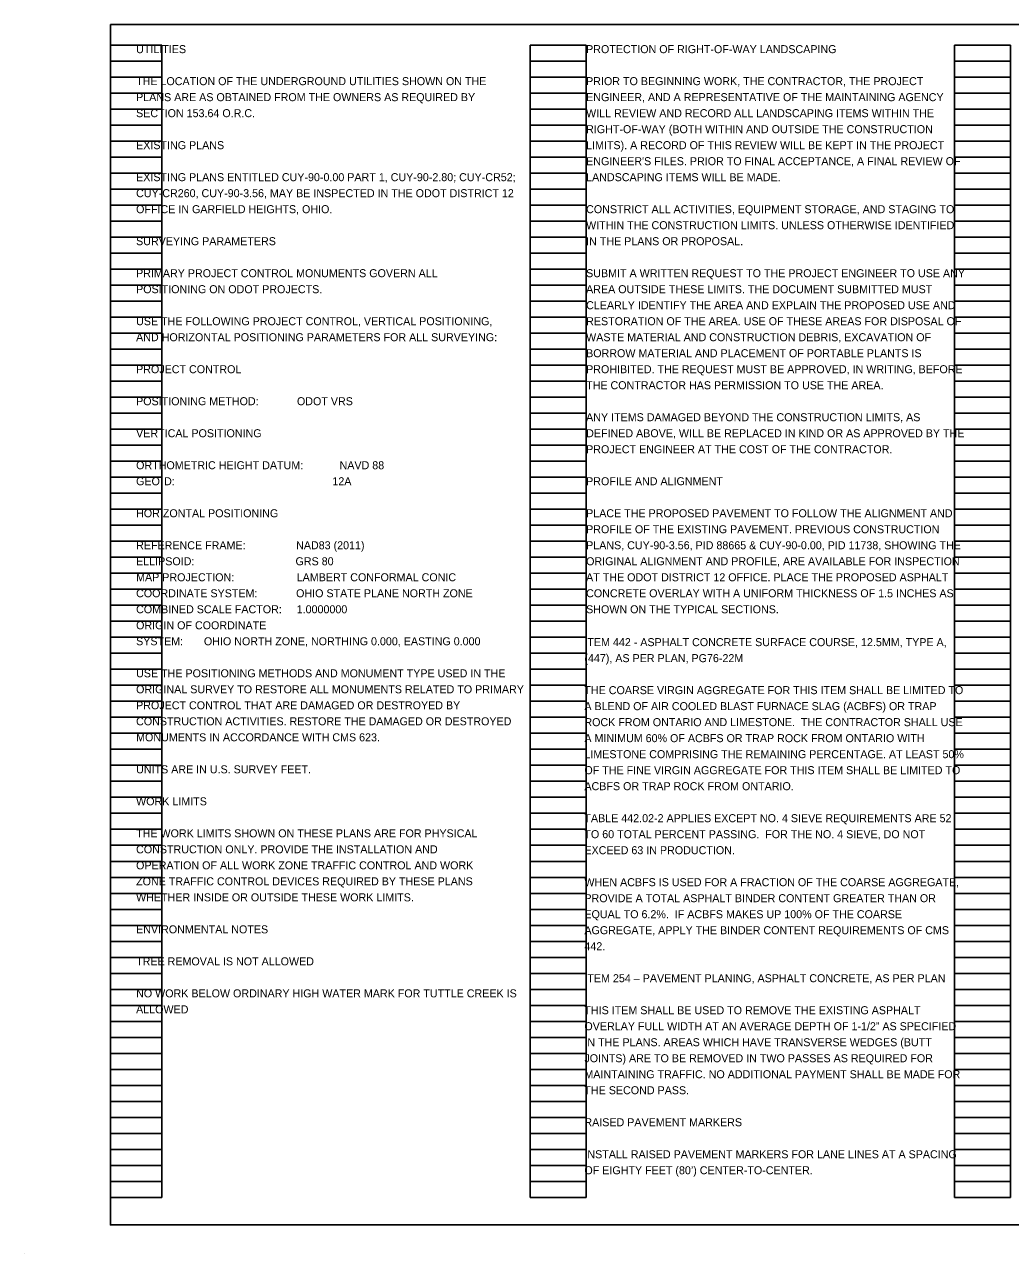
# Model space of a CAD drawing. Extents: x 0 to 2132911, y 0 to 658646.
# Drawn here: x 0 to 17.24, y 0 to 21.5 of the extents above; entities that cross this region are included whole.
import ezdxf

# ---------------------------------------------------------------- set-up
doc = ezdxf.new("R2010")
doc.units = 0
for name, color, linetype in [('SC_Scratch1', 7, 'Continuous'), ('SH_Data', 7, 'Continuous'), ('SH_Text', 7, 'Continuous')]:
    doc.layers.add(name, color=color, linetype=linetype)

msp = doc.modelspace()

# ---------------------------------------------------------------- linework, layer by layer
at = {"layer": 'SC_Scratch1'}
msp.add_lwpolyline([(1.5, 21.5), (32, 21.5), (32, 0.5), (1.5, 0.5)], close=True, dxfattribs=at)
at = {"layer": 'SH_Data'}
for p, q in [((1.5, 0.98), (1.5, 21.14)), ((1.5, 21.14), (2.4, 21.14)), ((2.4, 0.98), (2.4, 21.14)), ((8.84, 0.98), (8.84, 21.14)), ((8.84, 21.14), (9.82, 21.14)), ((9.82, 0.98), (9.82, 21.14)), ((16.26, 0.98), (16.26, 21.14)), ((16.26, 21.14), (17.24, 21.14)), ((17.24, 0.98), (17.24, 21.14)), ((1.5, 20.86), (2.4, 20.86)), ((8.84, 20.86), (9.82, 20.86)), ((16.26, 20.86), (17.24, 20.86)), ((1.5, 20.58), (2.4, 20.58)), ((8.84, 20.58), (9.82, 20.58)), ((16.26, 20.58), (17.24, 20.58)), ((1.5, 20.3), (2.4, 20.3)), ((8.84, 20.3), (9.82, 20.3)), ((16.26, 20.3), (17.24, 20.3)), ((1.5, 20.02), (2.4, 20.02)), ((8.84, 20.02), (9.82, 20.02)), ((16.26, 20.02), (17.24, 20.02)), ((1.5, 19.74), (2.4, 19.74)), ((8.84, 19.74), (9.82, 19.74)), ((16.26, 19.74), (17.24, 19.74)), ((1.5, 19.46), (2.4, 19.46)), ((8.84, 19.46), (9.82, 19.46)), ((16.26, 19.46), (17.24, 19.46)), ((1.5, 19.18), (2.4, 19.18)), ((8.84, 19.18), (9.82, 19.18)), ((16.26, 19.18), (17.24, 19.18)), ((1.5, 18.9), (2.4, 18.9)), ((8.84, 18.9), (9.82, 18.9)), ((16.26, 18.9), (17.24, 18.9)), ((1.5, 18.62), (2.4, 18.62)), ((8.84, 18.62), (9.82, 18.62)), ((16.26, 18.62), (17.24, 18.62)), ((1.5, 18.34), (2.4, 18.34)), ((8.84, 18.34), (9.82, 18.34)), ((16.26, 18.34), (17.24, 18.34)), ((1.5, 18.06), (2.4, 18.06)), ((8.84, 18.06), (9.82, 18.06)), ((16.26, 18.06), (17.24, 18.06)), ((1.5, 17.78), (2.4, 17.78)), ((8.84, 17.78), (9.82, 17.78)), ((16.26, 17.78), (17.24, 17.78)), ((1.5, 17.5), (2.4, 17.5)), ((8.84, 17.5), (9.82, 17.5)), ((16.26, 17.5), (17.24, 17.5)), ((1.5, 17.22), (2.4, 17.22)), ((8.84, 17.22), (9.82, 17.22)), ((16.26, 17.22), (17.24, 17.22)), ((1.5, 16.94), (2.4, 16.94)), ((8.84, 16.94), (9.82, 16.94)), ((16.26, 16.94), (17.24, 16.94)), ((1.5, 16.66), (2.4, 16.66)), ((8.84, 16.66), (9.82, 16.66)), ((16.26, 16.66), (17.24, 16.66)), ((1.5, 16.38), (2.4, 16.38)), ((8.84, 16.38), (9.82, 16.38)), ((16.26, 16.38), (17.24, 16.38)), ((1.5, 16.1), (2.4, 16.1)), ((8.84, 16.1), (9.82, 16.1)), ((16.26, 16.1), (17.24, 16.1)), ((1.5, 15.82), (2.4, 15.82)), ((8.84, 15.82), (9.82, 15.82)), ((16.26, 15.82), (17.24, 15.82)), ((1.5, 15.54), (2.4, 15.54)), ((8.84, 15.54), (9.82, 15.54)), ((16.26, 15.54), (17.24, 15.54)), ((1.5, 15.26), (2.4, 15.26)), ((8.84, 15.26), (9.82, 15.26)), ((16.26, 15.26), (17.24, 15.26)), ((1.5, 14.98), (2.4, 14.98)), ((8.84, 14.98), (9.82, 14.98)), ((16.26, 14.98), (17.24, 14.98)), ((1.5, 14.7), (2.4, 14.7)), ((8.84, 14.7), (9.82, 14.7)), ((16.26, 14.7), (17.24, 14.7)), ((1.5, 14.42), (2.4, 14.42)), ((8.84, 14.42), (9.82, 14.42)), ((16.26, 14.42), (17.24, 14.42)), ((1.5, 14.14), (2.4, 14.14)), ((8.84, 14.14), (9.82, 14.14)), ((16.26, 14.14), (17.24, 14.14)), ((1.5, 13.86), (2.4, 13.86)), ((8.84, 13.86), (9.82, 13.86)), ((16.26, 13.86), (17.24, 13.86)), ((1.5, 13.58), (2.4, 13.58)), ((8.84, 13.58), (9.82, 13.58)), ((16.26, 13.58), (17.24, 13.58)), ((1.5, 13.3), (2.4, 13.3)), ((8.84, 13.3), (9.82, 13.3)), ((16.26, 13.3), (17.24, 13.3)), ((1.5, 13.02), (2.4, 13.02)), ((8.84, 13.02), (9.82, 13.02)), ((16.26, 13.02), (17.24, 13.02)), ((1.5, 12.74), (2.4, 12.74)), ((8.84, 12.74), (9.82, 12.74)), ((16.26, 12.74), (17.24, 12.74)), ((1.5, 12.46), (2.4, 12.46)), ((8.84, 12.46), (9.82, 12.46)), ((16.26, 12.46), (17.24, 12.46)), ((1.5, 12.18), (2.4, 12.18)), ((8.84, 12.18), (9.82, 12.18)), ((16.26, 12.18), (17.24, 12.18)), ((1.5, 11.9), (2.4, 11.9)), ((8.84, 11.9), (9.82, 11.9)), ((16.26, 11.9), (17.24, 11.9)), ((1.5, 11.62), (2.4, 11.62)), ((8.84, 11.62), (9.82, 11.62)), ((16.26, 11.62), (17.24, 11.62)), ((1.5, 11.34), (2.4, 11.34)), ((8.84, 11.34), (9.82, 11.34)), ((16.26, 11.34), (17.24, 11.34)), ((1.5, 11.06), (2.4, 11.06)), ((8.84, 11.06), (9.82, 11.06)), ((16.26, 11.06), (17.24, 11.06)), ((1.5, 10.78), (2.4, 10.78)), ((8.84, 10.78), (9.82, 10.78)), ((16.26, 10.78), (17.24, 10.78)), ((1.5, 10.5), (2.4, 10.5)), ((8.84, 10.5), (9.82, 10.5)), ((16.26, 10.5), (17.24, 10.5)), ((1.5, 10.22), (2.4, 10.22)), ((8.84, 10.22), (9.82, 10.22)), ((16.26, 10.22), (17.24, 10.22)), ((1.5, 9.94), (2.4, 9.94)), ((8.84, 9.94), (9.82, 9.94)), ((16.26, 9.94), (17.24, 9.94)), ((1.5, 9.66), (2.4, 9.66)), ((8.84, 9.66), (9.82, 9.66)), ((16.26, 9.66), (17.24, 9.66)), ((1.5, 9.38), (2.4, 9.38)), ((8.84, 9.38), (9.82, 9.38)), ((16.26, 9.38), (17.24, 9.38)), ((1.5, 9.1), (2.4, 9.1)), ((8.84, 9.1), (9.82, 9.1)), ((16.26, 9.1), (17.24, 9.1)), ((1.5, 8.82), (2.4, 8.82)), ((8.84, 8.82), (9.82, 8.82)), ((16.26, 8.82), (17.24, 8.82)), ((1.5, 8.54), (2.4, 8.54)), ((8.84, 8.54), (9.82, 8.54)), ((16.26, 8.54), (17.24, 8.54)), ((1.5, 8.26), (2.4, 8.26)), ((8.84, 8.26), (9.82, 8.26)), ((16.26, 8.26), (17.24, 8.26)), ((1.5, 7.98), (2.4, 7.98)), ((8.84, 7.98), (9.82, 7.98)), ((16.26, 7.98), (17.24, 7.98)), ((1.5, 7.7), (2.4, 7.7)), ((8.84, 7.7), (9.82, 7.7)), ((16.26, 7.7), (17.24, 7.7)), ((1.5, 7.42), (2.4, 7.42)), ((8.84, 7.42), (9.82, 7.42)), ((16.26, 7.42), (17.24, 7.42)), ((1.5, 7.14), (2.4, 7.14)), ((8.84, 7.14), (9.82, 7.14)), ((16.26, 7.14), (17.24, 7.14)), ((1.5, 6.86), (2.4, 6.86)), ((8.84, 6.86), (9.82, 6.86)), ((16.26, 6.86), (17.24, 6.86)), ((1.5, 6.58), (2.4, 6.58)), ((8.84, 6.58), (9.82, 6.58)), ((16.26, 6.58), (17.24, 6.58)), ((1.5, 6.3), (2.4, 6.3)), ((8.84, 6.3), (9.82, 6.3)), ((16.26, 6.3), (17.24, 6.3)), ((1.5, 6.02), (2.4, 6.02)), ((8.84, 6.02), (9.82, 6.02)), ((16.26, 6.02), (17.24, 6.02)), ((1.5, 5.74), (2.4, 5.74)), ((8.84, 5.74), (9.82, 5.74)), ((16.26, 5.74), (17.24, 5.74)), ((1.5, 5.46), (2.4, 5.46)), ((8.84, 5.46), (9.82, 5.46)), ((16.26, 5.46), (17.24, 5.46)), ((1.5, 5.18), (2.4, 5.18)), ((8.84, 5.18), (9.82, 5.18)), ((16.26, 5.18), (17.24, 5.18)), ((1.5, 4.9), (2.4, 4.9)), ((8.84, 4.9), (9.82, 4.9)), ((16.26, 4.9), (17.24, 4.9)), ((1.5, 4.62), (2.4, 4.62)), ((8.84, 4.62), (9.82, 4.62)), ((16.26, 4.62), (17.24, 4.62)), ((1.5, 4.34), (2.4, 4.34)), ((8.84, 4.34), (9.82, 4.34)), ((16.26, 4.34), (17.24, 4.34)), ((1.5, 4.06), (2.4, 4.06)), ((8.84, 4.06), (9.82, 4.06)), ((16.26, 4.06), (17.24, 4.06)), ((1.5, 3.78), (2.4, 3.78)), ((8.84, 3.78), (9.82, 3.78)), ((16.26, 3.78), (17.24, 3.78)), ((1.5, 3.5), (2.4, 3.5)), ((8.84, 3.5), (9.82, 3.5)), ((16.26, 3.5), (17.24, 3.5)), ((1.5, 3.22), (2.4, 3.22)), ((8.84, 3.22), (9.82, 3.22)), ((16.26, 3.22), (17.24, 3.22)), ((1.5, 2.94), (2.4, 2.94)), ((8.84, 2.94), (9.82, 2.94)), ((16.26, 2.94), (17.24, 2.94)), ((1.5, 2.66), (2.4, 2.66)), ((8.84, 2.66), (9.82, 2.66)), ((16.26, 2.66), (17.24, 2.66)), ((1.5, 2.38), (2.4, 2.38)), ((8.84, 2.38), (9.82, 2.38)), ((16.26, 2.38), (17.24, 2.38)), ((1.5, 2.1), (2.4, 2.1)), ((8.84, 2.1), (9.82, 2.1)), ((16.26, 2.1), (17.24, 2.1)), ((1.5, 1.82), (2.4, 1.82)), ((8.84, 1.82), (9.82, 1.82)), ((16.26, 1.82), (17.24, 1.82)), ((1.5, 1.54), (2.4, 1.54)), ((8.84, 1.54), (9.82, 1.54)), ((16.26, 1.54), (17.24, 1.54)), ((1.5, 1.26), (2.4, 1.26)), ((8.84, 1.26), (9.82, 1.26)), ((16.26, 1.26), (17.24, 1.26)), ((1.5, 0.98), (2.4, 0.98)), ((8.84, 0.98), (9.82, 0.98)), ((16.26, 0.98), (17.24, 0.98)), ((0, 0), (0, 0))]:
    msp.add_line(p, q, dxfattribs=at)

# ---------------------------------------------------------------- texts
at = {"layer": 'SH_Text'}
for s, p in [('UTILITIES', (1.95, 21)), ('PROTECTION OF RIGHT-OF-WAY LANDSCAPING', (9.82, 21)), ('THE LOCATION OF THE UNDERGROUND UTILITIES SHOWN ON THE', (1.95, 20.44)), ('PRIOR TO BEGINNING WORK, THE CONTRACTOR, THE PROJECT ', (9.82, 20.44)), ('PLANS ARE AS OBTAINED FROM THE OWNERS AS REQUIRED BY', (1.95, 20.16)), ('ENGINEER, AND A REPRESENTATIVE OF THE MAINTAINING AGENCY ', (9.82, 20.16)), ('SECTION 153.64 O.R.C.', (1.95, 19.88)), ('WILL REVIEW AND RECORD ALL LANDSCAPING ITEMS WITHIN THE ', (9.82, 19.88)), ('RIGHT-OF-WAY (BOTH WITHIN AND OUTSIDE THE CONSTRUCTION ', (9.82, 19.6)), ('EXISTING PLANS', (1.95, 19.32)), ('LIMITS). A RECORD OF THIS REVIEW WILL BE KEPT IN THE PROJECT ', (9.82, 19.32)), ("ENGINEER'S FILES. PRIOR TO FINAL ACCEPTANCE, A FINAL REVIEW OF ", (9.82, 19.04)), ('EXISTING PLANS ENTITLED CUY-90-0.00 PART 1, CUY-90-2.80; CUY-CR52; ', (1.95, 18.76)), ('LANDSCAPING ITEMS WILL BE MADE.', (9.82, 18.76)), ('CUY-CR260, CUY-90-3.56, MAY BE INSPECTED IN THE ODOT DISTRICT 12 ', (1.95, 18.48)), ('OFFICE IN GARFIELD HEIGHTS, OHIO.', (1.95, 18.2)), ('CONSTRICT ALL ACTIVITIES, EQUIPMENT STORAGE, AND STAGING TO ', (9.82, 18.2)), ('WITHIN THE CONSTRUCTION LIMITS. UNLESS OTHERWISE IDENTIFIED ', (9.82, 17.92)), ('SURVEYING PARAMETERS', (1.95, 17.64)), ('IN THE PLANS OR PROPOSAL.', (9.82, 17.64)), ('PRIMARY PROJECT CONTROL MONUMENTS GOVERN ALL', (1.95, 17.08)), ('SUBMIT A WRITTEN REQUEST TO THE PROJECT ENGINEER TO USE ANY ', (9.82, 17.08)), ('POSITIONING ON ODOT PROJECTS. ', (1.95, 16.8)), ('AREA OUTSIDE THESE LIMITS. THE DOCUMENT SUBMITTED MUST ', (9.82, 16.8)), ('CLEARLY IDENTIFY THE AREA AND EXPLAIN THE PROPOSED USE AND ', (9.82, 16.52)), ('USE THE FOLLOWING PROJECT CONTROL, VERTICAL POSITIONING,', (1.95, 16.24)), ('RESTORATION OF THE AREA. USE OF THESE AREAS FOR DISPOSAL OF ', (9.82, 16.24)), ('AND HORIZONTAL POSITIONING PARAMETERS FOR ALL SURVEYING:', (1.95, 15.96)), ('WASTE MATERIAL AND CONSTRUCTION DEBRIS, EXCAVATION OF ', (9.82, 15.96)), ('BORROW MATERIAL AND PLACEMENT OF PORTABLE PLANTS IS ', (9.82, 15.68)), ('PROJECT CONTROL', (1.95, 15.4)), ('PROHIBITED. THE REQUEST MUST BE APPROVED, IN WRITING, BEFORE ', (9.82, 15.4)), ('THE CONTRACTOR HAS PERMISSION TO USE THE AREA.', (9.82, 15.12)), ('POSITIONING METHOD: ', (1.95, 14.84)), ('          ODOT VRS', (4.243, 14.84)), ('ANY ITEMS DAMAGED BEYOND THE CONSTRUCTION LIMITS, AS ', (9.82, 14.56)), ('VERTICAL POSITIONING', (1.95, 14.28)), ('DEFINED ABOVE, WILL BE REPLACED IN KIND OR AS APPROVED BY THE ', (9.82, 14.28)), ('PROJECT ENGINEER AT THE COST OF THE CONTRACTOR.', (9.82, 14)), ('ORTHOMETRIC HEIGHT DATUM: ', (1.95, 13.72)), ('         NAVD 88', (5.04, 13.72)), ('GEOI', (1.95, 13.44)), ('D:                                                     12A', (2.439, 13.44)), ('PROFILE AND ALIGNMENT', (9.82, 13.44)), ('HORIZONTAL POSITIONING', (1.95, 12.88)), ('PLACE THE PROPOSED PAVEMENT TO FOLLOW THE ALIGNMENT AND ', (9.82, 12.88)), ('PROFILE OF THE EXISTING PAVEMENT. PREVIOUS CONSTRUCTION ', (9.82, 12.6)), ('REFERENCE FRAME:                 NAD83 (2011)', (1.95, 12.32)), ('PLANS, CUY-90-3.56, PID 88665 & CUY-90-0.00, PID 11738, SHOWING THE ', (9.82, 12.32)), ('ELLIPSOID:                                  GRS 80', (1.95, 12.04)), ('ORIGINAL ALIGNMENT AND PROFILE, ARE AVAILABLE FOR INSPECTION ', (9.82, 12.04)), ('MAP PROJECTION:                     LAMBERT CONFORMAL CONIC', (1.95, 11.76)), ('AT THE ODOT DISTRICT 12 OFFICE. PLACE THE PROPOSED ASPHALT ', (9.82, 11.76)), ('COORDINATE SYSTEM:             OHIO STATE PLANE NORTH ZONE', (1.95, 11.48)), ('CONCRETE OVERLAY WITH A UNIFORM THICKNESS OF 1.5 INCHES AS ', (9.82, 11.48)), ('COMBINED SCALE FACTOR:     1.0000000', (1.95, 11.2)), ('SHOWN ON THE TYPICAL SECTIONS.', (9.82, 11.2)), ('ORIGIN OF COORDINATE', (1.95, 10.92)), ('SYSTEM:       OHIO NORTH ZONE, NORTHING 0.000, EASTING 0.000', (1.95, 10.64)), ('ITEM 442 - ASPHALT CONCRETE SURFACE COURSE, 12.5MM, TYPE A, ', (9.79, 10.625)), ('(447), AS PER PLAN, PG76-22M', (9.79, 10.345)), ('USE THE POSITIONING METHODS AND MONUMENT TYPE USED IN THE ', (1.95, 10.08)), ('ORIGINAL SURVEY TO RESTORE ALL MONUMENTS RELATED TO PRIMARY ', (1.95, 9.8)), ('THE COARSE VIRGIN AGGREGATE FOR THIS ITEM SHALL BE LIMITED TO ', (9.79, 9.785)), ('PROJECT CONTROL THAT ARE DAMAGED OR DESTROYED BY ', (1.95, 9.52)), ('A BLEND OF AIR COOLED BLAST FURNACE SLAG (ACBFS) OR TRAP ', (9.79, 9.505)), ('CONSTRUCTION ACTIVITIES. RESTORE THE DAMAGED OR DESTROYED ', (1.95, 9.24)), ('ROCK FROM ONTARIO AND LIMESTONE.  THE CONTRACTOR SHALL USE ', (9.79, 9.225)), ('MONUMENTS IN ACCORDANCE WITH CMS 623.', (1.95, 8.96)), ('A MINIMUM 60% OF ACBFS OR TRAP ROCK FROM ONTARIO WITH ', (9.79, 8.945)), ('LIMESTONE COMPRISING THE REMAINING PERCENTAGE. AT LEAST 50% ', (9.79, 8.665)), ('UNITS ARE IN U.S. SURVEY FEET.', (1.95, 8.4)), ('OF THE FINE VIRGIN AGGREGATE FOR THIS ITEM SHALL BE LIMITED TO ', (9.79, 8.385)), ('ACBFS OR TRAP ROCK FROM ONTARIO.', (9.79, 8.105)), ('WORK LIMITS', (1.95, 7.84)), ('TABLE 442.02-2 APPLIES EXCEPT NO. 4 SIEVE REQUIREMENTS ARE 52 ', (9.79, 7.545)), ('THE WORK LIMITS SHOWN ON THESE PLANS ARE FOR PHYSICAL', (1.95, 7.28)), ('TO 60 TOTAL PERCENT PASSING.  FOR THE NO. 4 SIEVE, DO NOT ', (9.79, 7.265)), ('CONSTRUCTION ONLY. PROVIDE THE INSTALLATION AND', (1.95, 7)), ('EXCEED 63 IN PRODUCTION.', (9.79, 6.985)), ('OPERATION OF ALL WORK ZONE TRAFFIC CONTROL AND WORK', (1.95, 6.72)), ('ZONE TRAFFIC CONTROL DEVICES REQUIRED BY THESE PLANS', (1.95, 6.44)), ('WHEN ACBFS IS USED FOR A FRACTION OF THE COARSE AGGREGATE, ', (9.79, 6.425)), ('WHETHER INSIDE OR OUTSIDE THESE WORK LIMITS.', (1.95, 6.16)), ('PROVIDE A TOTAL ASPHALT BINDER CONTENT GREATER THAN OR ', (9.79, 6.145)), ('EQUAL TO 6.2%.  IF ACBFS MAKES UP 100% OF THE COARSE ', (9.79, 5.865)), ('ENVIRONMENTAL NOTES', (1.95, 5.6)), ('AGGREGATE, APPLY THE BINDER CONTENT REQUIREMENTS OF CMS ', (9.79, 5.585)), ('442.', (9.79, 5.305)), ('TREE REMOVAL IS NOT ALLOWED', (1.95, 5.04)), ('ITEM 254 – PAVEMENT PLANING, ASPHALT CONCRETE, AS PER PLAN', (9.79, 4.745)), ('NO WORK BELOW ORDINARY HIGH WATER MARK FOR TUTTLE CREEK IS ', (1.95, 4.48)), ('ALLOWED', (1.95, 4.2)), ('THIS ITEM SHALL BE USED TO REMOVE THE EXISTING ASPHALT ', (9.79, 4.185)), ('OVERLAY FULL WIDTH AT AN AVERAGE DEPTH OF 1-1/2” AS SPECIFIED ', (9.79, 3.905)), ('IN THE PLANS. AREAS WHICH HAVE TRANSVERSE WEDGES (BUTT ', (9.79, 3.625)), ('JOINTS) ARE TO BE REMOVED IN TWO PASSES AS REQUIRED FOR ', (9.79, 3.345)), ('MAINTAINING TRAFFIC. NO ADDITIONAL PAYMENT SHALL BE MADE FOR ', (9.79, 3.065)), ('THE SECOND PASS.', (9.79, 2.785)), ('RAISED PAVEMENT MARKERS', (9.79, 2.225)), ('INSTALL RAISED PAVEMENT MARKERS FOR LANE LINES AT A SPACING ', (9.79, 1.665)), ('OF EIGHTY FEET (80’) CENTER-TO-CENTER.', (9.79, 1.385))]:
    msp.add_text(s, height=0.14, dxfattribs=at).set_placement(p)

doc.saveas('drawing.dxf')
